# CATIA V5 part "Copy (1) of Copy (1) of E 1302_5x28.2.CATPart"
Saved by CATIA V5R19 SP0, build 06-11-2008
Part number: Copy (1) of Copy (1) of E 1302_5x28.2
Nomenclature: E 1302_5x28
Source: Unknown
Description: PART-E 1302_5x28-DESC
Bounding box of the stored display mesh (mm): x -2.5 to 2.5, y -2.5 to 2.5, z 0 to 28
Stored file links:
  C:\Users\jsmid\Desktop\DP_Smidak_Forma LEGO\Copy (1) of Copy (1) of E 1302_5x28.2.CATPart
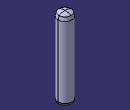
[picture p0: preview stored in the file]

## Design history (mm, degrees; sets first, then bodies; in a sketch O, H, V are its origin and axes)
Body1 "E 1302_5x28" (main body)
  Solid1: solid without history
